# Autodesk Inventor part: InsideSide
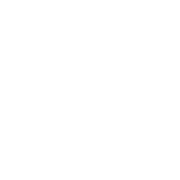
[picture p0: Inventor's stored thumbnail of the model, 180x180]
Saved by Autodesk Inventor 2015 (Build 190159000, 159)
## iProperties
Created: 2016-02
Part Number: InsideSide
Material: Wood (Birch)
Document SubType Name: Modeling
Designer: Hafliði
Density: 0.55 g/cm^3
Appearance: Birch - Natural Polished
Mass: 154 g
Surface Area: 628 cm^2
Volume: 280 cm^3
Author: Hafliði
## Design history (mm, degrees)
sketch "Sketch1"
  geometry: L1 (-100, 70)-(100, 70); L2 (100, 70)-(100, -70); L3 (100, -70)-(-100, -70); L4 (-100, -70)-(-100, 70); L5 (-100, 70)-(100, -70); L6 (100, 70)-(-100, -70); 1 further point
  constraints: 12 end point, 2 midpoint, 2 parallel, 1 horizontal, 1 perpendicular
  dimensions: "d0" = 200 distance of L2.end L3.end; "d1" = 140 distance of L1.end L2.end
extrude "Extrusion1" new body sketch "Sketch1" distance "d2" = 10; taper "d3" = 0 deg
body "Solid1"
